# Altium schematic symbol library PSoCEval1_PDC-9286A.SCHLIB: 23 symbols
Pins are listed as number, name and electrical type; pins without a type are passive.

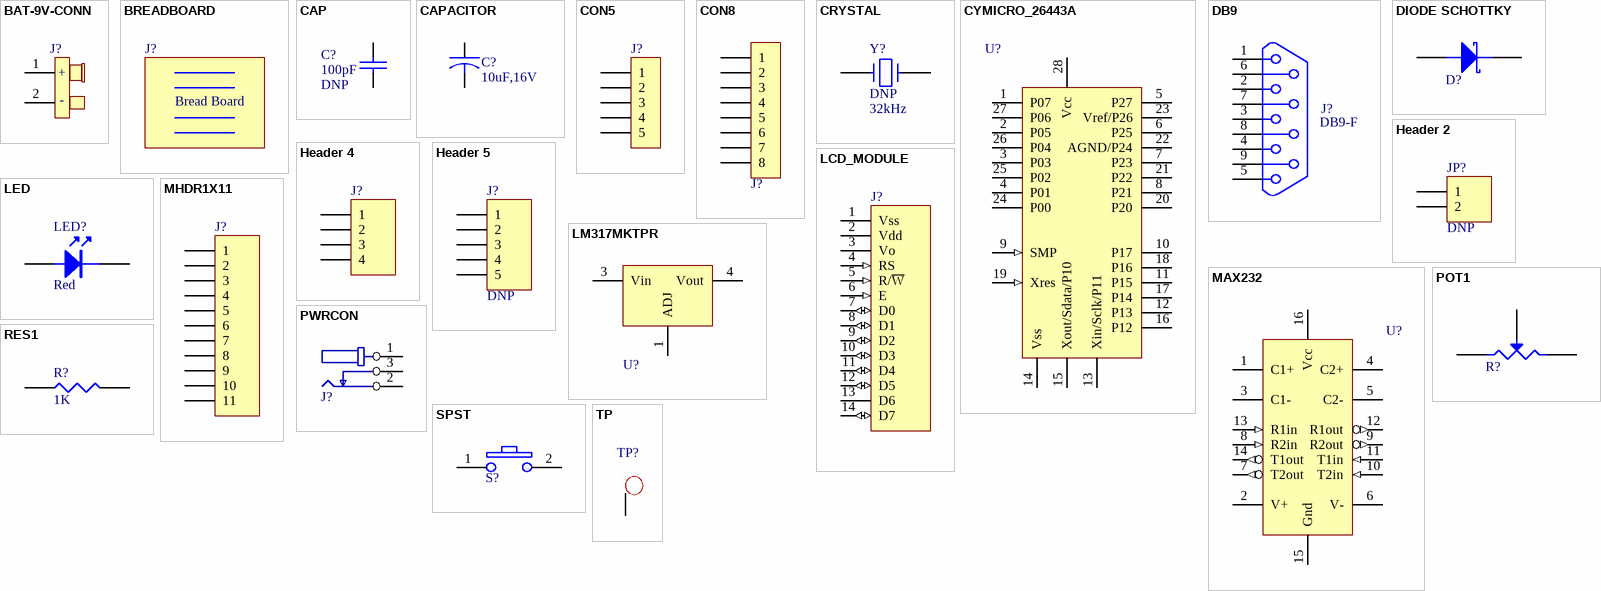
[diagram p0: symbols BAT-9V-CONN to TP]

## BAT-9V-CONN
designator J?
9-Volt batter connector; Vender: Digikey; VPN: 593K-ND, 594K-ND; MFG: Keystone Electronics; MFGPN: 593, 594
footprint 9VBAT
pins: 1 P, 2 N

## BREADBOARD
designator J?
3M solderless breadboard super strip; VPN: 923273-ND; Vender: Digikey; MFG: Parallax; MFGPN: 700-00012
footprint 3M-SUPERSTRIP
footprint BBOARD_1.8x1.4

## CAP
designator C?, comment DNP  value 100pF
Capacitor; Vender: Digikey; VPN: PCC101CGCT-ND; MFG: Panasonic; MFGPN: ECJ-2VC1H101J
footprint 0805
pins: 1, 2

## CAPACITOR
designator C?  value 10uF,16V
Capacitor; Vender: Digikey; VPN: 493-2173-2-ND; MFG: Nichicon; MFGPN: UWT1C100MCL1GB
footprint CAP_Nich_WT4-4.5
pins: 1, 2

## CON5
designator J?
ISSP connector; Vender: Digikey; VPN: WM4203-ND; Value: 5; MFG: Molex/Waldom
footprint ISPCON
pins: 1, 2, 3, 4, 5

## CON8
designator J?
8-Pin Header, Female; Vender: Digikey; VPN: 929850-01-36-ND; Value: 8; MFG: 3M/ESD; MFGPN: 929850-01-36-10
footprint HDR8X1
pins: 1, 2, 3, 4, 5, 6, 7, 8

## CRYSTAL
designator Y?, comment DNP  value 32kHz
Crystal; Vender: Digikey; VPN: X801-ND; MFG: ECS Inc; MFGPN: ECS-3X8
footprint XTAL32K
pins: 1, 2

## CYMICRO_26443A
designator U?
CMS 27443, w/ socket; Vender: Cypress; VPN: CY8C27443; MFG: Mill-Max MFG Corp; MFGPN: 110-93-328-41-001000
footprint 28PDIP
footprint 28SOIC
footprint 28SSOP
footprint DIP-28-ZIF
pins: 1 P07, 2 P05, 3 P03, 4 P01, 5 P27, 6 P25, 7 P23, 8 P21, 9 SMP (in), 10 P17, 11 P15, 12 P13, 13 Xin/Sclk/P11, 14 Vss (power), 15 Xout/Sdata/P10, 16 P12, 17 P14, 18 P16, 19 Xres (in), 20 P20, 21 P22, 22 AGND/P24, 23 Vref/P26, 24 P00, 25 P02, 26 P04, 27 P06, 28 Vcc (power)

## DB9
designator J?  value DB9-F
Female DB-9; Vender: Digikey; VPN: A23301-ND; MFGPN: 747844-2; MFG: AMP/Tyco Electronics
footprint DB-9/M
footprint DB9F
pins: 1, 2, 3, 4, 5, 6, 7, 8, 9

## DIODE SCHOTTKY
designator D?
Schottky Diode; Vender: Digikey; VPN: S1ADICT-ND; MFG: Diodes Inc; MFGPN: S1A-13
footprint SMA-A
pins: 1 A, 2 K

## Header 2
designator JP?, comment DNP
Header, 2-Pin, Male; Manufacturer: Generic Components; Class I: Connector; Vender: Digikey; VPN: S1011-36-ND; Value: 2; MFG: Sullins Electronics Corp; MFGPN: PZC36SAAN
footprint HDR2x1
signal-integrity model Connector
pins: 1, 2

## Header 4
designator J?
Header, 4-Pin; Vender: Digikey; VPN: 929850-01-36-ND; Value: 4; MFG: 3M/ESD; MFGPN: 929850-01-36-10
footprint HDR1X4 (Connector; Header; 4 Position)
signal-integrity model Connector
pins: 1, 2, 3, 4

## Header 5
designator J?, comment DNP
Ground conn.; Manufacturer: Generic Components; Class I: Connector; Vender: NA
footprint HDR5X1-GND
signal-integrity model Connector
pins: 1, 2, 3, 4, 5

## LCD_MODULE
designator J?
14-Pin header, Female; Vender: Digikey; VPN: 929850-01-36-ND; Value: 14; MFG: 3M/ESD; MFGPN: 929850-01-36-10
footprint HDR7X2
footprint HDR14X1
pins: 1 Vss (power), 2 Vdd (power), 3 Vo (power), 4 RS (in), 5 R/~{W} (in), 6 E (in), 7 D0 (io), 8 D1 (io), 9 D2 (io), 10 D3 (io), 11 D4 (io), 12 D5 (io), 13 D6, 14 D7 (io)

## LED
designator LED?  value Red
Red LED; Vender: Digikey; VPN: 67-1552-2-ND; MFG: Lumex Opto; MFGPN: SML-LXT0805IW-TR
footprint LED0805
pins: A 1, K 2

## LM317MKTPR
designator U?, comment ADJ Vreg  (value not drawn)
Adjustable Voltage Regulator; Manufacturer: TI; Vender: Digikey; VPN: 296-9537-2-ND; MFGPN: LM317MKTPR; MFG: Texas Instruments
footprint KTP02 (PowerFLEX (D-PAK/TO-252-AA); 3 Leads (1 Cropped); Body 9.7 (inc. leads) x 6.2 mm (LxW max))
pins: 1 ADJ, 3 Vin, 4 Vout

## MAX232
designator U?
RS-232 tranceiver (1.0uF Caps); Vender: Digikey; VPN: 296-13098-2-ND; MFG: Texas Instruments; MFGPN: MAX3232IDR
footprint DIP16
footprint SO-16
pins: 1 C1+, 2 V+, 3 C1-, 4 C2+, 5 C2-, 6 V-, 7 T2out (out), 8 R2in (in), 9 R2out (out), 10 T2in (in), 11 T1in (in), 12 R1out (out), 13 R1in (in), 14 T1out (out), 15 Gnd (power), 16 Vcc (power)

## MHDR1X11
designator J?
Header, 11-Pin; Manufacturer: Generic Components; Class I: Connector; VPN: 929850-01-36-ND; Vender: Digikey; Value: 11; MFG: 3M/ESD; MFGPN: 929850-01-36-10
footprint HDR11X1
signal-integrity model Connector
pins: 1, 2, 3, 4, 5, 6, 7, 8, 9, 10, 11

## POT1
designator R?
Potentiometer; Vender: Digikey; VPN: D4AA14-ND; MFGPN: EVN-D8AA03B14; MFG: Panasonic
footprint POT_EVND8A
pins: 1, 2, 3 W

## PWRCON
designator J?
Power connector; Vender: Digikey; VPN: CP-102A-ND; MFG: CUI Inc; MFGPN: PJ-102A
footprint PWRCON
pins: 1, 2, 3

## RES1
designator R?  value 1K
Resistor, SMT; Vender: Digikey; VPN: P1.0KACT-ND; MFGPN: ERJ-6GEYJ102V; MFG: Panasonic
footprint R2012-0805
pins: 1, 2

## SPST
designator S?
Swtich, SPST; Vender: Digikey; VPN: SW403-ND; MFGPN: B3F-1022; MFG: Omron
footprint STDSW
pins: 1 C, 2 NO

## TP
designator TP?
Simple Test point; VPN: 5006K-ND; Vender: Digikey; MFGPN: 5006; MFG: Keystone Electronics
footprint TP1
footprint TP64
pins: 1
